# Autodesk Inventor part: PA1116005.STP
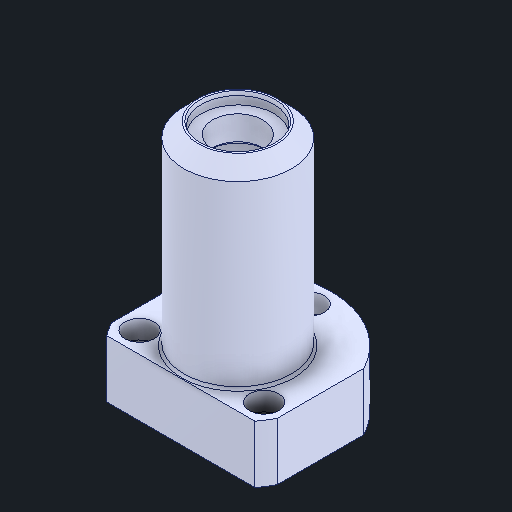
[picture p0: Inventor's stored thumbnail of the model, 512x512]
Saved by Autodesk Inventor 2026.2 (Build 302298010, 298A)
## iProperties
Created: 1601-01
Part Number: PA1116005.STP
Material: Generic
Description: NOT SPECIFIED
Document SubType Name: Modeling
Designer: cpEwe
Density: 1 g/cm^3
Appearance: Default
Author: cpEwe
Revision Number: 1
Sending System: SOLIDWORKS 2024
Nomenclature: PA1116005
Part Number: PA1116005
Source: MADE
Definition: design
Last Saved Date: 2026-03-14
last saved by: cpEwe
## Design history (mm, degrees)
feature "PA1116005"
feature "Composite1"
body "Solid1"
body "Srf1"
